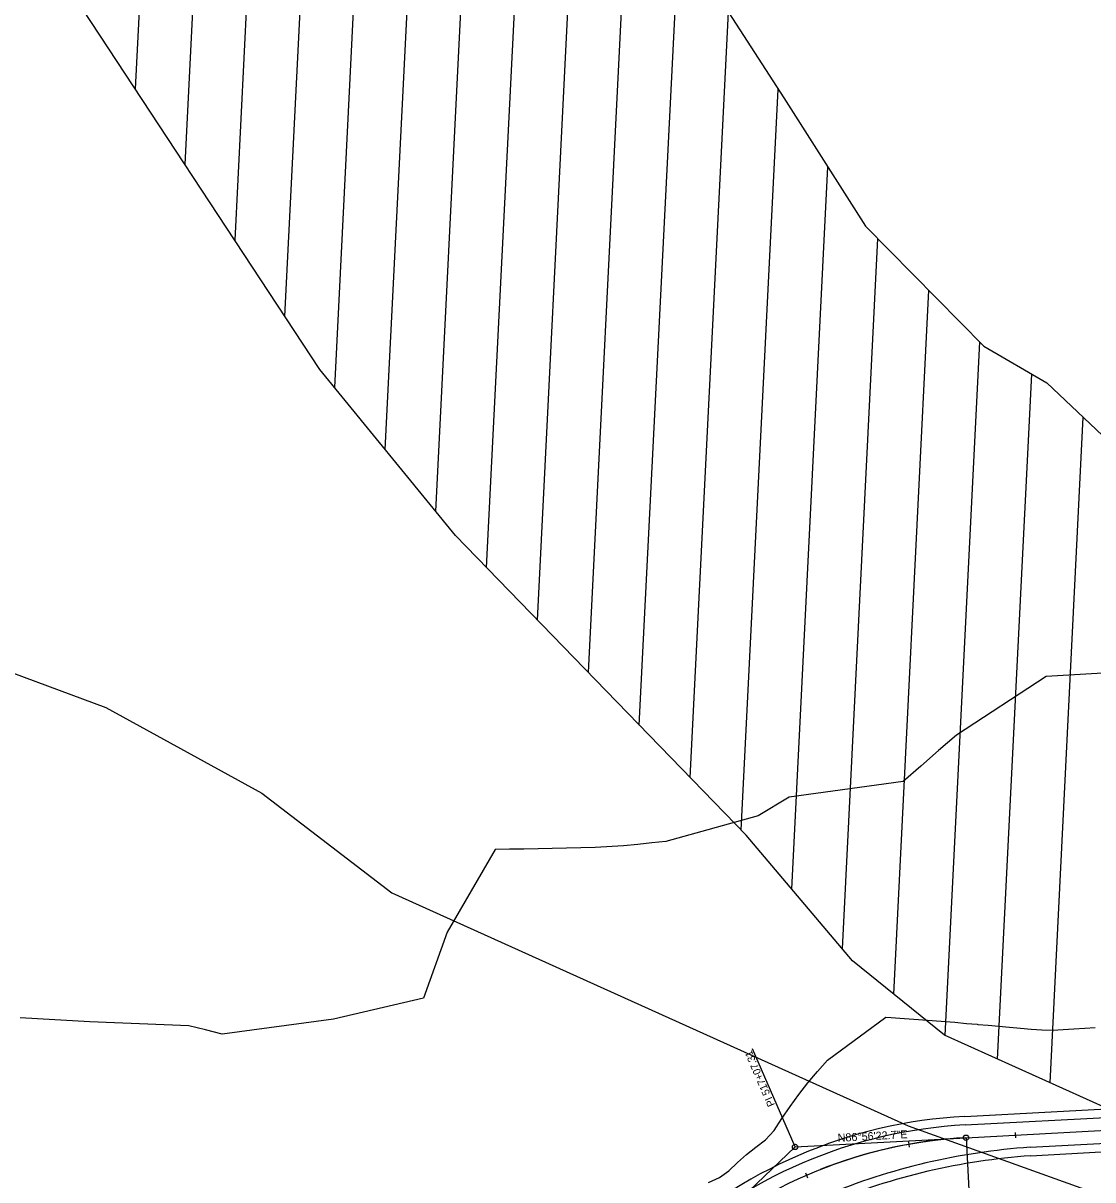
# Model space of a CAD drawing. Extents: x 1300404 to 1323571, y 234004 to 252077.
# Drawn here: x 1309592 to 1310592, y 241789 to 242870 of the extents above; entities that cross this region are included whole.
import ezdxf

# ---------------------------------------------------------------- set-up
doc = ezdxf.new("R2010")
doc.units = 0
for name, color, linetype in [('R_Floodway', 7, 'Continuous'), ('R_Flooplain', 7, 'Continuous'), ('R_Lane Edge', 7, 'Continuous'), ('R_Shoulder', 7, 'Continuous'), ('S_CONTOUR_ANNOT', 7, 'Continuous'), ('S_CONTOUR_MINOR', 7, 'Continuous'), ('S_CROSS_DRAIN', 7, 'Continuous'), ('S_EDGE_PAVEMENT_ANNOT', 7, 'Continuous'), ('S_ELECTRIC_UTILITIES_ANNOT', 7, 'Continuous'), ('S_LANDSCAPING_ANNOT', 7, 'Continuous'), ('S_POOL', 7, 'Continuous'), ('S_SIGN', 7, 'Continuous'), ('S_UTL_PT_SYM', 7, 'Continuous')]:
    doc.layers.add(name, color=color, linetype=linetype)

msp = doc.modelspace()

# ---------------------------------------------------------------- linework, layer by layer
at = {"layer": 'R_Floodway'}
for p, q in [((1309697.3, 242809), (1309735, 243561.9)), ((1309743.8, 242738.2), (1309782.9, 243518.6)), ((1309790.3, 242667.5), (1309831.1, 243481.3)), ((1309836.8, 242596.7), (1309878.7, 243432)), ((1309883.5, 242529.8), (1309925.7, 243372)), ((1309930.7, 242471.9), (1309972.5, 243305.9)), ((1309977.9, 242414.1), (1310019.2, 243239.8)), ((1310025.3, 242361.6), (1310066, 243173.7)), ((1310072.9, 242312.6), (1310112.7, 243106.8)), ((1310120.5, 242263.5), (1310158.6, 243023.4)), ((1310168.1, 242214.5), (1310204.9, 242949.2)), ((1310215.7, 242165.4), (1310251.6, 242880.6)), ((1310263.3, 242116.3), (1310298, 242808.9)), ((1310310.6, 242061.1), (1310344.4, 242736.1)), ((1310357.9, 242005.2), (1310391.1, 242669.1)), ((1310405.8, 241962.9), (1310438.8, 242620.8)), ((1310454, 241924.2), (1310486.4, 242572.5)), ((1310502.9, 241902.2), (1310535, 242542.5)), ((1310551.9, 241880.2), (1310583, 242502.1))]:
    msp.add_line(p, q, dxfattribs=at)
for points in [[(1312719.3, 241174), (1312375.3, 241167.2), (1311696.9, 241341.7), (1311497.5, 241419.5), (1311333.8, 241508.8), (1311059.1, 241652.1), (1310740.8, 241795.1), (1310453.3, 241924.5), (1310367.2, 241994.2), (1310267.8, 242111.7), (1309996.2, 242391.6), (1309869.7, 242546.7), (1309624.5, 242919.6)], [(1310244.9, 242890.8), (1310303.3, 242800.7), (1310379.6, 242680.8), (1310490.2, 242568.7), (1310549, 242534.3), (1310676, 242414.2), (1310731.6, 242363), (1310810.3, 242291.3), (1310887.6, 242241.4), (1310974.9, 242195.9), (1311031.6, 242168.8), (1311109.7, 242133.4), (1311173.8, 242108.4), (1311242.7, 242083.2), (1311339.3, 242032.3), (1311351, 242024.5), (1311431.5, 241940.6), (1311405.2, 241750.8)]]:
    msp.add_lwpolyline(points, dxfattribs=at)
at = {"layer": 'R_Flooplain'}
msp.add_lwpolyline([(1308850.4, 242983.4), (1308921.9, 242863.7), (1309009.8, 242685), (1309044.1, 242596.2), (1309055.9, 242542.4), (1309352.1, 242367.8), (1309503.2, 242292.4), (1309669.5, 242230.8), (1309815.5, 242150.9), (1309936.7, 242057.6), (1310419.4, 241839.8), (1310733.2, 241727.2), (1311043.7, 241597.8), (1311103.2, 241577.9), (1311152.8, 241553.6), (1311178, 241525.7), (1311328.5, 241486.7), (1311553.1, 241381), (1311870.3, 241290), (1312137.5, 241213.6), (1312460.1, 241035.3)], dxfattribs=at)
at = {"layer": 'R_Lane Edge'}
for p, q in [((1310472.7, 241840.7), (1310917.8, 241864.5)), ((1310533.3, 241819.9), (1310919, 241840.6))]:
    msp.add_line(p, q, dxfattribs=at)
for centre, radius, start, end in [((1310496.4, 241397), 444.4, 93.0604, 133.6667), ((1310575, 241212.4), 608.9, 93.9267, 112.4996)]:
    msp.add_arc(centre, radius, start, end, dxfattribs=at)
at = {"layer": 'R_Shoulder'}
for p, q in [((1310472.3, 241848.7), (1310917.3, 241872.5)), ((1310533.7, 241812), (1310919.5, 241832.6))]:
    msp.add_line(p, q, dxfattribs=at)
for centre, radius, start, end in [((1310496.4, 241397), 452.4, 93.0604, 133.6667), ((1310575, 241212.4), 600.9, 93.9325, 112.5014)]:
    msp.add_arc(centre, radius, start, end, dxfattribs=at)
at = {"layer": 'S_CONTOUR_ANNOT'}
for p, q in [((1310313.6, 241820.2), (1310473.4, 241828.8)), ((1310197.9, 241709.8), (1310313.6, 241820.2))]:
    msp.add_line(p, q, dxfattribs=at)
at = {"layer": 'S_CROSS_DRAIN'}
msp.add_line((1310473.4, 241828.8), (1310918.4, 241852.6), dxfattribs=at)
at = {"layer": 'S_EDGE_PAVEMENT_ANNOT'}
for points in [[(1310313.6, 241820.2), (1310273.9, 241912)], [(1310473.4, 241828.8), (1310479.2, 241719.2)]]:
    msp.add_lwpolyline(points, dxfattribs=at)
at = {"layer": 'S_ELECTRIC_UTILITIES_ANNOT'}
for points in [[(1310659.8, 242266.4), (1310548.2, 242259.9), (1310464.4, 242205.1), (1310447.8, 242190.6), (1310431.2, 242176.1), (1310414.6, 242161.6), (1310308.2, 242147.2), (1310279.2, 242129.5), (1310193, 242105.7), (1310179.8, 242104.3), (1310166.6, 242102.9), (1310153.4, 242101.6), (1310126.8, 242099.9), (1310113.5, 242099.7), (1310100.1, 242099.4), (1310086.8, 242099.2), (1310073.5, 242098.9), (1310060.1, 242098.6), (1310046.8, 242098.4), (1310033.5, 242098.1), (1309988.7, 242021), (1309966.4, 241959.1), (1309882.3, 241939.5), (1309778.3, 241925.7), (1309762.7, 241929.5), (1309747.1, 241933.3), (1309724, 241934.2), (1309700.9, 241935.2), (1309677.7, 241936.2), (1309654.6, 241937.2), (1309638.3, 241938.1), (1309622, 241938.9), (1309605.8, 241939.8), (1309589.5, 241940.7)], [(1310232.9, 241787.1), (1310242.9, 241791.7), (1310251.8, 241797.9), (1310259.9, 241805.5), (1310268.3, 241813), (1310277, 241820.1), (1310285.9, 241826.9), (1310294.1, 241835.7), (1310301.4, 241846.8), (1310309.1, 241858), (1310317.2, 241869.2), (1310325.7, 241880), (1310334.7, 241890.7), (1310344.1, 241901.3), (1310398.6, 241941.4), (1310403.6, 241941.1), (1310411.7, 241940.6), (1310424.6, 241939.6), (1310437.5, 241938.8), (1310450.2, 241937.7), (1310462.8, 241936.7), (1310473.9, 241935.7), (1310483.9, 241934.8), (1310484.4, 241934.7), (1310494, 241933.9), (1310504, 241933), (1310514.1, 241932.1), (1310524.2, 241931.2), (1310534.2, 241930.3), (1310544.3, 241929.5), (1310554.3, 241929.3), (1310564.3, 241929.9), (1310574.3, 241930.5), (1310584.3, 241931.2), (1310594.2, 241931.8)]]:
    msp.add_lwpolyline(points, dxfattribs=at)
at = {"layer": 'S_LANDSCAPING_ANNOT'}
msp.add_line((1310473.4, 241828.8), (1310918.4, 241852.6), dxfattribs=at)
for centre in [(1310313.6, 241820.2), (1310473.4, 241828.8)]:
    msp.add_circle(centre, 2.5, dxfattribs=at)
for start, end in [(93.0604, 133.6667), (93.0604, 111.6332), (94.9846, 111.6332), (94.9846, 111.6332)]:
    msp.add_arc((1310496.4, 241397), 432.4, start, end, dxfattribs=at)
at = {"layer": 'S_POOL'}
msp.add_arc((1310575, 241212.4), 608.9, 93.9267, 112.4996, dxfattribs=at)
at = {"layer": 'S_SIGN'}
for points in [[(1310519.4, 241833.7), (1310519.6, 241828.7)], [(1310419.5, 241825), (1310420.4, 241820.1)], [(1310323.5, 241796), (1310325.4, 241791.4)]]:
    msp.add_lwpolyline(points, dxfattribs=at)

# ---------------------------------------------------------------- texts
at = {"layer": 'S_CONTOUR_MINOR'}
msp.add_text('N86%%d56\'22.7"E', height=7.5, rotation=3.0604, dxfattribs=at).set_placement((1310353.7, 241824.9))
at = {"layer": 'S_UTL_PT_SYM'}
msp.add_text('PI 517+07.31', height=7, rotation=113.3635, dxfattribs=at).set_placement((1310295, 241859.6))

doc.saveas('drawing.dxf')
